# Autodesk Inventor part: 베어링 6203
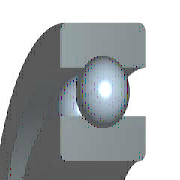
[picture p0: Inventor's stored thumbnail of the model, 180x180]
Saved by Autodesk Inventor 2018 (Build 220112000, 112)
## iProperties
IsCustomPart: 0
Created: 2016-05
Part Number: 베어링 6203
Material: 강철, 연강
Description: 깊은 그루브 볼 베어링
Document SubType Name: Modeling
Standard: KS B 2023
Designer: mduedu
Standards Organization: KS
Language: ko-KR
Size Designation: 6203 - 17 x 40 x 12
Categories: <MemberInstance><Categories><Category DisplayName="샤프트 부품" InternalName="7f7aeb1f-a693-4053-b835-cee3144e0d98" Mnemonic="SHFT"><Category DisplayName="베어링" Inter
Density: 1 g/cm^3
Appearance: 노란색
Author: mduedu
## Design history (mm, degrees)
sketch "스케치" dims "d0" = 5.98 (= -0.26 x WD + 0.26 x BD)
  geometry: L1 (3.01, 14.25)-(8.99, 14.25); L2 (6, 14.25)-(6, 11.26); L3 (6, 14.25)-(6, 17.24); L4 (3.778, 12.249)-(0, 12.249); L5 (0, 8.5)-(12, 8.5); L6 (3.778, 16.251)-(0, 16.251); L7 (0, 20)-(12, 20); L8 (12, 8.5)-(12, 12.249); L9 (8.222, 12.249)-(12, 12.249); L10 (8.222, 16.251)-(12, 16.251); L11 (12, 20)-(12, 16.251); L12 (-1.4, 0)-(8.4, 0) reference; L13 (0, -0.3)-(0, 5.3) reference
  constraints: 22 end point, 4 point on line, 2 collinear, 2 perpendicular, 2 symmetric about line, 1 midpoint, 1 parallel, 14 other
  dimensions: "d9" = 17 diameter of L5 L12 (= WD); "d11" = 40 diameter of L7 L12 (= BD); "d12" = 12 distance between parallel lines of L8 L13 (= KB); "d13" = 24.498 diameter of L9 L12 (= 0.326 x BD + 0.674 x WD)
revolve "본체" stored, may be unused: angle "d6" = 90 deg
revolve "볼" stored, may be unused: angle "d7" = 90 deg
pattern_circular "IDS_ARRAYBALL[SIMPL:T]" dims angle "d3" = 360 deg
body "Solid1"
fillet "모깎기1" dims "d1" = 0.6 (= KRS)
other parameters: "WD" = 17 [user parameter; used in 5 equation terms], "BD" = 40 [user parameter; used in 5 equation terms], "KB" = 12 [user parameter; used in 1 equation term], "KRS" = 0.6 [user parameter; used in 1 equation term], "d4" = 0, "d5" = 0, "d8" = 0, "d14" = 0, "d15" = 0, "BBA" = 0 [user parameter], "BC0" = 4750000 [user parameter], "BC" = 9560000 [user parameter], "WR" = 8.5 (= 0.5 x WD) [user parameter]
